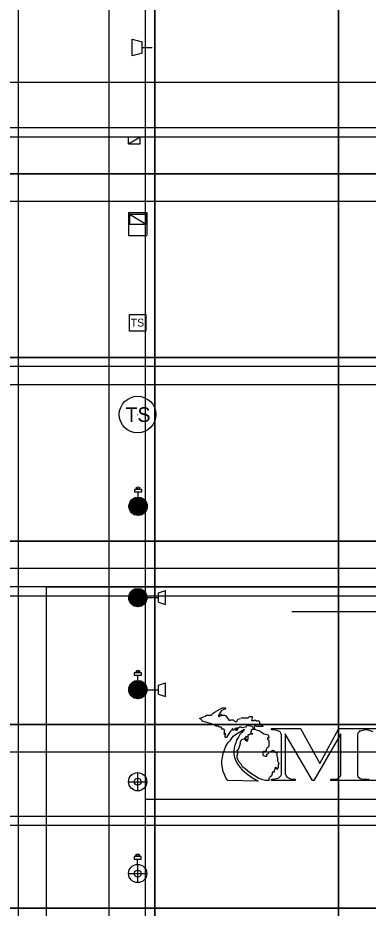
# Model space of a CAD drawing. Extents: x 2146475 to 2147951, y 2147003 to 2148003.
# Drawn here: x 2147543.5 to 2147619.9, y 2147343 to 2147537 of the extents above; entities that cross this region are included whole.
import ezdxf

# ---------------------------------------------------------------- set-up
doc = ezdxf.new("R2010")
doc.units = 0
for name, color, linetype in [('Sheet_Border_Block_LightingInventory', 7, 'Continuous'), ('Sheet_Border_Line_Wt2', 7, 'Continuous'), ('Sheet_Border_Plan_Dual', 7, 'Continuous'), ('Sheet_Border_PlanOverProf1_Grid+Sta+EL_04_040+08_080', 7, 'Continuous'), ('Sheet_Border_PlanOverProf1_Grid+Sta+EL_10_100+20_200', 7, 'Continuous'), ('Sheet_Border_Prof3_Grid+Sta+EL_04_040+08_080', 7, 'Continuous'), ('Sheet_Border_Prof3_Grid+Sta+EL_10_100+20_200', 7, 'Continuous'), ('Sheet_Border_TitleSheet', 7, 'Continuous'), ('Sheet_Border_TitleSheet_ConsultantBlock', 7, 'Continuous'), ('Sheet_Border_XS_Grid', 7, 'Continuous'), ('Signal_Ctrl_TS_Controller_Fdn_Pr_BaseMount_$Ea', 7, 'Continuous'), ('Signal_Ctrl_TS_Controller_Pr_$Ea', 7, 'Continuous'), ('Signal_Mt_All_TS_Ped_Ex_GS', 7, 'Continuous'), ('Signal_Pole_Ped+PushButton_Ex_GS', 7, 'Continuous'), ('Signal_Pole_Ped_Ex_GS', 7, 'Continuous'), ('Signal_Pole_Steel_Ex_GS', 7, 'Continuous'), ('Util_NoID_Ex_Handhole_Round_GS', 7, 'Continuous'), ('Util_NoID_Ex_Handhole_Square_GS', 7, 'Continuous')]:
    doc.layers.add(name, color=color, linetype=linetype)

msp = doc.modelspace()

# ---------------------------------------------------------------- linework, layer by layer
at = {"layer": 'Sheet_Border_Block_LightingInventory'}
for p, q in [((2147549.81, 2147124.95), (2147549.81, 2147412.95)), ((2147549.81, 2147412.95), (2147871.41, 2147412.95))]:
    msp.add_line(p, q, dxfattribs=at)
for points in [[(2147592.2, 2147384.43), (2147593.78, 2147384.43), (2147594.07, 2147384.72), (2147594.64, 2147384.72), (2147594.64, 2147384.43), (2147594.5, 2147383.85), (2147595.08, 2147383.85), (2147595.22, 2147384), (2147595.36, 2147383.85), (2147595.51, 2147383.85), (2147595.51, 2147383.71), (2147595.94, 2147383.85), (2147596.23, 2147383.57), (2147596.23, 2147383.13), (2147596.37, 2147383.13), (2147596.66, 2147382.85), (2147596.66, 2147382.7), (2147596.95, 2147382.7), (2147596.95, 2147382.56), (2147595.65, 2147382.56), (2147595.36, 2147382.7), (2147595.22, 2147382.7), (2147595.08, 2147382.41), (2147595.22, 2147382.27), (2147595.08, 2147382.13), (2147594.93, 2147382.13), (2147594.79, 2147382.41), (2147594.64, 2147382.56), (2147593.92, 2147382.7), (2147593.49, 2147382.85), (2147593.35, 2147382.7), (2147593.2, 2147382.41), (2147592.48, 2147382.27), (2147592.2, 2147382.41), (2147591.91, 2147382.41), (2147591.48, 2147382.13), (2147591.19, 2147381.69), (2147591.04, 2147381.69), (2147591.04, 2147381.84), (2147591.19, 2147381.98), (2147591.33, 2147382.27), (2147591.04, 2147382.13), (2147590.9, 2147382.13), (2147590.76, 2147381.98), (2147590.47, 2147381.69), (2147590.32, 2147382.13), (2147590.18, 2147381.84), (2147589.89, 2147381.55), (2147589.6, 2147381.12), (2147589.03, 2147380.11), (2147588.88, 2147380.11), (2147588.74, 2147380.25), (2147588.74, 2147380.54), (2147588.88, 2147380.97), (2147588.74, 2147380.97), (2147588.6, 2147380.83), (2147588.45, 2147380.97), (2147588.6, 2147381.12), (2147588.6, 2147381.84), (2147588.45, 2147381.98), (2147588.02, 2147381.98), (2147588.02, 2147382.13), (2147587.88, 2147382.27), (2147588.02, 2147382.27), (2147587.88, 2147382.41), (2147587.59, 2147382.41), (2147587.3, 2147382.56), (2147587.01, 2147382.85), (2147586.87, 2147382.56), (2147586.58, 2147382.85), (2147586.44, 2147382.85), (2147586.15, 2147382.99), (2147585.28, 2147383.28), (2147583.7, 2147383.71), (2147583.7, 2147383.85), (2147583.41, 2147384.14), (2147583.41, 2147384.29), (2147583.12, 2147384.29), (2147584.56, 2147384.86), (2147584.56, 2147385.01), (2147585.72, 2147385.01), (2147586.15, 2147385.44), (2147586.58, 2147385.73), (2147587.59, 2147386.3), (2147588.16, 2147386.59), (2147588.74, 2147386.59), (2147588.88, 2147386.45), (2147588.74, 2147386.3), (2147588.6, 2147386.3), (2147588.31, 2147386.16), (2147588.02, 2147386.01), (2147587.88, 2147385.87), (2147587.59, 2147385.44), (2147587.44, 2147385.15), (2147587.3, 2147385.01), (2147587.3, 2147384.72), (2147587.44, 2147384.72), (2147587.59, 2147384.86), (2147587.73, 2147385.15), (2147588.02, 2147385.15), (2147587.73, 2147384.86)], [(2147587.73, 2147384.86), (2147588.16, 2147385.01), (2147588.6, 2147385.01), (2147588.88, 2147384.86), (2147589.17, 2147384.43), (2147589.32, 2147384.29), (2147589.6, 2147383.85), (2147590.04, 2147384), (2147590.47, 2147384), (2147590.76, 2147383.71), (2147591.19, 2147383.57), (2147591.33, 2147383.71), (2147591.33, 2147383.85), (2147591.48, 2147384.14), (2147592.05, 2147384.29)], [(2147621, 2147381.41), (2147619.7, 2147381.84), (2147619.12, 2147381.84), (2147619.12, 2147382.13), (2147627.19, 2147382.13)], [(2147597.96, 2147380.11), (2147597.96, 2147379.82), (2147597.96, 2147379.68), (2147598.24, 2147379.53), (2147598.24, 2147378.24), (2147598.1, 2147377.95), (2147597.96, 2147377.95), (2147597.81, 2147377.81), (2147597.67, 2147377.52), (2147597.67, 2147377.23), (2147597.52, 2147377.09), (2147597.09, 2147377.09), (2147596.95, 2147376.94), (2147596.95, 2147376.37), (2147597.09, 2147376.22), (2147597.52, 2147376.08), (2147597.81, 2147376.08), (2147597.81, 2147376.51), (2147597.96, 2147376.51), (2147598.24, 2147376.8), (2147598.24, 2147376.94), (2147598.1, 2147376.94), (2147598.68, 2147377.09), (2147599.11, 2147377.37), (2147599.4, 2147377.23), (2147599.54, 2147376.94), (2147599.97, 2147376.8), (2147599.97, 2147376.08), (2147600.12, 2147375.79), (2147600.12, 2147375.07), (2147600.4, 2147374.49), (2147600.4, 2147374.35), (2147600.26, 2147374.35), (2147600.26, 2147373.63), (2147599.97, 2147373.2), (2147599.83, 2147373.63), (2147599.68, 2147373.63), (2147599.54, 2147373.49), (2147599.54, 2147373.2), (2147599.4, 2147372.91), (2147599.4, 2147372.62), (2147598.96, 2147372.62), (2147598.96, 2147372.19), (2147598.82, 2147371.76), (2147598.68, 2147371.61), (2147598.53, 2147371.61), (2147598.39, 2147371.33), (2147598.24, 2147371.18), (2147598.24, 2147370.75), (2147597.52, 2147370.75), (2147596.95, 2147370.89), (2147596.08, 2147371.18), (2147594.07, 2147372.48), (2147593.06, 2147373.34), (2147592.48, 2147373.77), (2147592.2, 2147374.35), (2147591.76, 2147374.78), (2147591.48, 2147375.36), (2147591.33, 2147375.79), (2147591.33, 2147376.22), (2147591.48, 2147376.65), (2147591.48, 2147376.94), (2147591.33, 2147377.37), (2147591.62, 2147377.52), (2147591.76, 2147377.95), (2147592.05, 2147378.81), (2147591.91, 2147378.96), (2147592.05, 2147379.1), (2147592.2, 2147379.53), (2147592.34, 2147379.68), (2147592.77, 2147379.82), (2147592.92, 2147379.68), (2147593.06, 2147380.11), (2147593.35, 2147380.4), (2147593.2, 2147379.82), (2147593.2, 2147379.39), (2147593.49, 2147379.68), (2147593.64, 2147379.68), (2147593.35, 2147379.25), (2147593.64, 2147379.53), (2147593.78, 2147379.82), (2147593.78, 2147380.69), (2147593.92, 2147380.83), (2147594.07, 2147380.83), (2147594.21, 2147380.97), (2147594.79, 2147380.97), (2147594.79, 2147380.97), (2147594.5, 2147380.97), (2147594.36, 2147381.26), (2147594.5, 2147381.55), (2147594.5, 2147381.84), (2147594.64, 2147381.98), (2147595.22, 2147381.98), (2147595.51, 2147381.84), (2147595.94, 2147381.69), (2147596.08, 2147381.69), (2147596.37, 2147381.55), (2147596.52, 2147381.41), (2147597.24, 2147380.97), (2147598.1, 2147380.69), (2147598.24, 2147379.97)], [(2147598.24, 2147379.97), (2147598.1, 2147380.11)], [(2147627.62, 2147370.75), (2147619.12, 2147370.75), (2147619.12, 2147371.04), (2147620.13, 2147371.04)]]:
    msp.add_lwpolyline(points, dxfattribs=at)
for points in [[(2147605.16, 2147382.13), (2147609.33, 2147374.49), (2147613.51, 2147382.13), (2147619.7, 2147382.13), (2147619.7, 2147381.84), (2147619.27, 2147381.84), (2147618.12, 2147381.55), (2147617.97, 2147381.55), (2147617.97, 2147381.41), (2147617.68, 2147381.12), (2147617.54, 2147380.83), (2147617.54, 2147371.9), (2147617.68, 2147371.61), (2147618.12, 2147371.18), (2147618.69, 2147371.04), (2147619.7, 2147371.04), (2147619.7, 2147370.75), (2147611.78, 2147370.75), (2147611.78, 2147371.04), (2147612.93, 2147371.04), (2147613.36, 2147371.18), (2147613.51, 2147371.47), (2147613.8, 2147371.61), (2147613.94, 2147371.9), (2147613.94, 2147380.97), (2147608.04, 2147370.75), (2147607.75, 2147370.75), (2147601.84, 2147380.97), (2147601.84, 2147372.33), (2147602.13, 2147371.61), (2147602.56, 2147371.33), (2147603.14, 2147371.04), (2147604, 2147371.04), (2147604, 2147370.75), (2147598.82, 2147370.75), (2147598.82, 2147371.04), (2147598.96, 2147371.04), (2147599.97, 2147371.18), (2147600.4, 2147371.33), (2147600.55, 2147371.47), (2147600.84, 2147371.76), (2147600.98, 2147372.05), (2147600.98, 2147380.83), (2147600.84, 2147381.12), (2147600.69, 2147381.41), (2147600.4, 2147381.55), (2147599.97, 2147381.69), (2147599.25, 2147381.84), (2147598.82, 2147381.84), (2147598.82, 2147382.13)], [(2147589.32, 2147370.75), (2147588.88, 2147371.33), (2147588.6, 2147372.05), (2147588.31, 2147372.77), (2147588.02, 2147374.35), (2147588.02, 2147375.07), (2147588.31, 2147376.65), (2147588.88, 2147378.24), (2147589.32, 2147378.96), (2147589.89, 2147379.53), (2147590.47, 2147380.4), (2147591.19, 2147380.97), (2147592.92, 2147381.98), (2147592.34, 2147381.26), (2147591.91, 2147380.83), (2147591.62, 2147380.25), (2147591.19, 2147379.53), (2147591.04, 2147378.96), (2147590.76, 2147378.24), (2147590.61, 2147377.37), (2147590.61, 2147376.51), (2147590.76, 2147375.79), (2147591.19, 2147374.78), (2147591.62, 2147374.06), (2147592.34, 2147373.2), (2147593.35, 2147372.33), (2147594.5, 2147371.47), (2147595.94, 2147370.61)]]:
    msp.add_lwpolyline(points, close=True, dxfattribs=at)
at = {"layer": 'Sheet_Border_Line_Wt2'}
msp.add_line((2147543.69, 2147124.95), (2147543.69, 2147920.95), dxfattribs=at)
at = {"layer": 'Sheet_Border_Plan_Dual'}
msp.add_line((2146555.41, 2147522.95), (2147871.41, 2147522.95), dxfattribs=at)
at = {"layer": 'Sheet_Border_PlanOverProf1_Grid+Sta+EL_04_040+08_080'}
for p, q in [((2146555.41, 2147522.95), (2147871.41, 2147522.95)), ((2147813.41, 2147512.95), (2146613.41, 2147512.95)), ((2147563.41, 2147512.95), (2147563.41, 2147138.95)), ((2147613.41, 2147512.95), (2147613.41, 2147138.95)), ((2147813.41, 2147462.95), (2146613.41, 2147462.95)), ((2147813.41, 2147412.95), (2146613.41, 2147412.95)), ((2147813.41, 2147362.95), (2146613.41, 2147362.95))]:
    msp.add_line(p, q, dxfattribs=at)
at = {"layer": 'Sheet_Border_PlanOverProf1_Grid+Sta+EL_10_100+20_200'}
for p, q in [((2146555.41, 2147522.95), (2147871.41, 2147522.95)), ((2147813.41, 2147502.95), (2146613.41, 2147502.95)), ((2147573.41, 2147502.95), (2147573.41, 2147158.95)), ((2147613.41, 2147502.95), (2147613.41, 2147158.95)), ((2147813.41, 2147462.95), (2146613.41, 2147462.95)), ((2147813.41, 2147422.95), (2146613.41, 2147422.95)), ((2147813.41, 2147382.95), (2146613.41, 2147382.95)), ((2147813.41, 2147342.95), (2146613.41, 2147342.95))]:
    msp.add_line(p, q, dxfattribs=at)
at = {"layer": 'Sheet_Border_Prof3_Grid+Sta+EL_04_040+08_080'}
for p, q in [((2147563.41, 2147910.95), (2147563.41, 2147136.95)), ((2147613.41, 2147910.95), (2147613.41, 2147136.95)), ((2147813.41, 2147510.95), (2146613.41, 2147510.95)), ((2147813.41, 2147460.95), (2146613.41, 2147460.95)), ((2147813.41, 2147410.95), (2146613.41, 2147410.95)), ((2147813.41, 2147360.95), (2146613.41, 2147360.95))]:
    msp.add_line(p, q, dxfattribs=at)
at = {"layer": 'Sheet_Border_Prof3_Grid+Sta+EL_10_100+20_200'}
for p, q in [((2147573.41, 2147896.95), (2147573.41, 2147152.95)), ((2147613.41, 2147896.95), (2147613.41, 2147152.95)), ((2147813.41, 2147496.95), (2146613.41, 2147496.95)), ((2147813.41, 2147456.95), (2146613.41, 2147456.95)), ((2147813.41, 2147416.95), (2146613.41, 2147416.95)), ((2147813.41, 2147376.95), (2146613.41, 2147376.95))]:
    msp.add_line(p, q, dxfattribs=at)
at = {"layer": 'Sheet_Border_TitleSheet'}
for p, q in [((2147571.41, 2147366.72), (2147871.41, 2147366.72)), ((2147571.41, 2147124.95), (2147571.41, 2147366.72))]:
    msp.add_line(p, q, dxfattribs=at)
at = {"layer": 'Sheet_Border_TitleSheet_ConsultantBlock'}
for p, q in [((2147571.41, 2147366.72), (2147571.41, 2147666.72)), ((2147603.25, 2147407.59), (2147769.16, 2147407.59))]:
    msp.add_line(p, q, dxfattribs=at)
at = {"layer": 'Sheet_Border_XS_Grid'}
for p, q in [((2147573.41, 2147142.95), (2147573.41, 2147902.95)), ((2147613.41, 2147142.95), (2147613.41, 2147902.95)), ((2146573.41, 2147502.95), (2147853.41, 2147502.95)), ((2146573.41, 2147462.95), (2147853.41, 2147462.95)), ((2146573.41, 2147422.95), (2147853.41, 2147422.95)), ((2146573.41, 2147382.95), (2147853.41, 2147382.95)), ((2146573.41, 2147342.95), (2147853.41, 2147342.95))]:
    msp.add_line(p, q, dxfattribs=at)
at = {"layer": 'Signal_Ctrl_TS_Controller_Fdn_Pr_BaseMount_$Ea'}
for p, q in [((2147567.7, 2147494.51), (2147571.7, 2147494.51)), ((2147567.7, 2147494.51), (2147567.7, 2147489.52)), ((2147567.87, 2147494.18), (2147567.87, 2147492.01)), ((2147567.87, 2147494.18), (2147571.53, 2147494.18)), ((2147567.87, 2147494.18), (2147571.53, 2147492.01)), ((2147571.53, 2147494.18), (2147571.53, 2147492.01)), ((2147571.7, 2147494.51), (2147571.7, 2147489.52)), ((2147567.7, 2147492.01), (2147571.7, 2147492.01)), ((2147567.7, 2147489.52), (2147571.7, 2147489.52))]:
    msp.add_line(p, q, dxfattribs=at)
at = {"layer": 'Signal_Ctrl_TS_Controller_Pr_$Ea'}
for p, q in [((2147567.7, 2147511.05), (2147570.19, 2147511.05)), ((2147567.7, 2147509.52), (2147567.7, 2147511.05)), ((2147567.7, 2147509.52), (2147570.19, 2147511.05)), ((2147570.19, 2147509.52), (2147570.19, 2147511.05)), ((2147567.7, 2147509.52), (2147570.19, 2147509.52))]:
    msp.add_line(p, q, dxfattribs=at)
at = {"layer": 'Signal_Mt_All_TS_Ped_Ex_GS'}
for p, q in [((2147568.46, 2147528.7), (2147568.46, 2147532.3)), ((2147568.46, 2147532.3), (2147570.66, 2147531.75)), ((2147570.66, 2147529.25), (2147570.66, 2147531.75)), ((2147570.66, 2147530.5), (2147572.85, 2147530.5)), ((2147570.66, 2147529.25), (2147568.46, 2147528.7)), ((2147574.19, 2147411.63), (2147575.71, 2147412.14)), ((2147574.19, 2147409.63), (2147574.19, 2147411.63)), ((2147575.71, 2147409.14), (2147575.71, 2147412.14)), ((2147571.69, 2147410.62), (2147574.19, 2147410.62)), ((2147574.19, 2147409.63), (2147575.71, 2147409.14)), ((2147574.2, 2147391.56), (2147575.71, 2147392.07)), ((2147575.71, 2147389.08), (2147575.71, 2147392.07)), ((2147571.7, 2147390.56), (2147574.2, 2147390.56)), ((2147574.2, 2147389.56), (2147574.2, 2147391.56)), ((2147574.2, 2147389.56), (2147575.71, 2147389.08))]:
    msp.add_line(p, q, dxfattribs=at)
at = {"layer": 'Signal_Pole_Ped+PushButton_Ex_GS'}
for p, q in [((2147569.29, 2147434.45), (2147569.58, 2147434.45)), ((2147569.58, 2147434.45), (2147569.58, 2147434.2)), ((2147569.75, 2147432.49), (2147569.75, 2147433.66)), ((2147569.93, 2147434.45), (2147570.22, 2147434.45)), ((2147569.93, 2147434.45), (2147569.93, 2147434.2)), ((2147569.75, 2147432.49), (2147569.75, 2147432.49)), ((2147569.24, 2147394.51), (2147569.53, 2147394.51)), ((2147569.53, 2147394.51), (2147569.53, 2147394.26)), ((2147569.88, 2147394.51), (2147570.17, 2147394.51)), ((2147569.88, 2147394.51), (2147569.88, 2147394.26)), ((2147569.71, 2147392.55), (2147569.71, 2147393.72)), ((2147569.71, 2147392.55), (2147569.71, 2147392.55)), ((2147569.19, 2147354.45), (2147569.48, 2147354.45)), ((2147569.48, 2147354.45), (2147569.48, 2147354.2)), ((2147569.66, 2147352.49), (2147569.66, 2147353.66)), ((2147569.83, 2147354.45), (2147570.13, 2147354.45)), ((2147569.83, 2147354.45), (2147569.83, 2147354.2)), ((2147569.66, 2147352.49), (2147569.66, 2147352.49))]:
    msp.add_line(p, q, dxfattribs=at)
for points in [[(2147568.97, 2147433.66), (2147570.54, 2147433.66), (2147570.54, 2147434.2), (2147568.97, 2147434.2)], [(2147568.92, 2147393.72), (2147570.49, 2147393.72), (2147570.49, 2147394.26), (2147568.92, 2147394.26)], [(2147568.88, 2147353.66), (2147570.44, 2147353.66), (2147570.44, 2147354.2), (2147568.88, 2147354.2)]]:
    msp.add_lwpolyline(points, close=True, dxfattribs=at)
for centre in [(2147569.75, 2147434.45), (2147569.71, 2147394.51), (2147569.66, 2147354.45)]:
    msp.add_ellipse(centre, major_axis=(0.467, 0), ratio=0.42688, start_param=0, end_param=3.141593, dxfattribs=at)
at = {"layer": 'Signal_Pole_Ped_Ex_GS'}
for p, q in [((2147567.77, 2147430.62), (2147571.74, 2147430.62)), ((2147571.73, 2147430.75), (2147567.78, 2147430.75)), ((2147571.71, 2147430.87), (2147567.8, 2147430.87)), ((2147571.68, 2147431), (2147567.83, 2147431)), ((2147571.65, 2147431.12), (2147567.86, 2147431.12)), ((2147571.6, 2147431.25), (2147567.91, 2147431.25)), ((2147571.55, 2147431.37), (2147567.96, 2147431.37)), ((2147571.48, 2147431.49), (2147568.03, 2147431.49)), ((2147568.11, 2147431.62), (2147571.4, 2147431.62)), ((2147571.31, 2147431.74), (2147568.2, 2147431.74)), ((2147571.2, 2147431.87), (2147568.31, 2147431.87)), ((2147571.08, 2147431.99), (2147568.44, 2147431.99)), ((2147570.92, 2147432.12), (2147568.59, 2147432.12)), ((2147570.72, 2147432.24), (2147568.79, 2147432.24)), ((2147570.45, 2147432.37), (2147569.06, 2147432.37)), ((2147571.75, 2147430.5), (2147567.76, 2147430.5)), ((2147571.74, 2147430.38), (2147567.77, 2147430.38)), ((2147571.73, 2147430.25), (2147567.78, 2147430.25)), ((2147571.71, 2147430.13), (2147567.8, 2147430.13)), ((2147571.68, 2147430), (2147567.83, 2147430)), ((2147571.65, 2147429.88), (2147567.86, 2147429.88)), ((2147567.91, 2147429.75), (2147571.6, 2147429.75)), ((2147571.55, 2147429.63), (2147567.96, 2147429.63)), ((2147571.48, 2147429.5), (2147568.03, 2147429.5)), ((2147571.4, 2147429.38), (2147568.11, 2147429.38)), ((2147571.31, 2147429.26), (2147568.2, 2147429.26)), ((2147571.2, 2147429.13), (2147568.31, 2147429.13)), ((2147571.07, 2147429.01), (2147568.44, 2147429.01)), ((2147570.92, 2147428.88), (2147568.59, 2147428.88)), ((2147568.79, 2147428.76), (2147570.72, 2147428.76)), ((2147570.45, 2147428.63), (2147569.06, 2147428.63)), ((2147569.84, 2147428.51), (2147569.67, 2147428.51)), ((2147571.59, 2147411.25), (2147567.81, 2147411.25)), ((2147571.55, 2147411.37), (2147567.85, 2147411.37)), ((2147571.49, 2147411.49), (2147567.91, 2147411.49)), ((2147571.43, 2147411.62), (2147567.97, 2147411.62)), ((2147568.05, 2147411.74), (2147571.35, 2147411.74)), ((2147571.26, 2147411.87), (2147568.14, 2147411.87)), ((2147571.15, 2147411.99), (2147568.25, 2147411.99)), ((2147571.02, 2147412.12), (2147568.38, 2147412.12)), ((2147570.86, 2147412.24), (2147568.54, 2147412.24)), ((2147570.67, 2147412.37), (2147568.73, 2147412.37)), ((2147570.4, 2147412.49), (2147569, 2147412.49)), ((2147567.71, 2147410.75), (2147571.69, 2147410.75)), ((2147571.69, 2147410.62), (2147567.71, 2147410.62)), ((2147571.69, 2147410.5), (2147567.71, 2147410.5)), ((2147571.68, 2147410.87), (2147567.72, 2147410.87)), ((2147571.68, 2147410.38), (2147567.72, 2147410.38)), ((2147571.66, 2147411), (2147567.74, 2147411)), ((2147571.66, 2147410.25), (2147567.74, 2147410.25)), ((2147571.63, 2147411.12), (2147567.77, 2147411.12)), ((2147571.63, 2147410.13), (2147567.77, 2147410.13)), ((2147571.59, 2147410), (2147567.81, 2147410)), ((2147567.85, 2147409.88), (2147571.55, 2147409.88)), ((2147571.49, 2147409.75), (2147567.91, 2147409.75)), ((2147571.43, 2147409.63), (2147567.97, 2147409.63)), ((2147571.35, 2147409.5), (2147568.05, 2147409.5)), ((2147571.26, 2147409.38), (2147568.14, 2147409.38)), ((2147571.15, 2147409.26), (2147568.25, 2147409.26)), ((2147571.02, 2147409.13), (2147568.38, 2147409.13)), ((2147570.86, 2147409.01), (2147568.54, 2147409.01)), ((2147568.73, 2147408.88), (2147570.67, 2147408.88)), ((2147570.4, 2147408.76), (2147569, 2147408.76)), ((2147569.79, 2147408.63), (2147569.61, 2147408.63)), ((2147571.15, 2147391.93), (2147568.26, 2147391.93)), ((2147571.03, 2147392.05), (2147568.39, 2147392.05)), ((2147570.87, 2147392.18), (2147568.54, 2147392.18)), ((2147570.67, 2147392.3), (2147568.74, 2147392.3)), ((2147570.4, 2147392.42), (2147569.01, 2147392.42)), ((2147571.7, 2147390.56), (2147567.71, 2147390.56)), ((2147567.72, 2147390.68), (2147571.69, 2147390.68)), ((2147571.69, 2147390.43), (2147567.72, 2147390.43)), ((2147571.68, 2147390.81), (2147567.73, 2147390.81)), ((2147571.68, 2147390.31), (2147567.73, 2147390.31)), ((2147571.66, 2147390.93), (2147567.75, 2147390.93)), ((2147571.66, 2147390.19), (2147567.75, 2147390.19)), ((2147571.64, 2147391.06), (2147567.78, 2147391.06)), ((2147571.64, 2147390.06), (2147567.78, 2147390.06)), ((2147571.6, 2147391.18), (2147567.81, 2147391.18)), ((2147571.6, 2147389.94), (2147567.81, 2147389.94)), ((2147571.55, 2147391.31), (2147567.86, 2147391.31)), ((2147571.5, 2147391.43), (2147567.92, 2147391.43)), ((2147571.43, 2147391.55), (2147567.98, 2147391.55)), ((2147568.06, 2147391.68), (2147571.35, 2147391.68)), ((2147571.26, 2147391.8), (2147568.15, 2147391.8)), ((2147567.86, 2147389.81), (2147571.55, 2147389.81)), ((2147571.5, 2147389.69), (2147567.92, 2147389.69)), ((2147571.43, 2147389.56), (2147567.98, 2147389.56)), ((2147571.35, 2147389.44), (2147568.06, 2147389.44)), ((2147571.26, 2147389.32), (2147568.15, 2147389.32)), ((2147571.15, 2147389.19), (2147568.26, 2147389.19)), ((2147571.03, 2147389.07), (2147568.39, 2147389.07)), ((2147570.87, 2147388.94), (2147568.54, 2147388.94)), ((2147568.74, 2147388.82), (2147570.67, 2147388.82)), ((2147570.4, 2147388.69), (2147569.01, 2147388.69)), ((2147569.8, 2147388.57), (2147569.62, 2147388.57))]:
    msp.add_line(p, q, dxfattribs=at)
for centre in [(2147569.76, 2147430.5), (2147569.7, 2147410.62), (2147569.71, 2147390.56)]:
    msp.add_circle(centre, 1.99, dxfattribs=at)
at = {"layer": 'Signal_Pole_Steel_Ex_GS'}
for p, q in [((2147569.66, 2147372.49), (2147569.66, 2147368.51)), ((2147567.67, 2147370.5), (2147571.64, 2147370.5)), ((2147569.66, 2147352.49), (2147569.66, 2147348.51)), ((2147567.67, 2147350.5), (2147571.65, 2147350.5))]:
    msp.add_line(p, q, dxfattribs=at)
for centre, radius in [((2147569.66, 2147370.5), 1.99), ((2147569.66, 2147370.5), 0.757), ((2147569.66, 2147350.51), 1.99), ((2147569.66, 2147350.5), 0.757)]:
    msp.add_circle(centre, radius, dxfattribs=at)
at = {"layer": 'Util_NoID_Ex_Handhole_Round_GS'}
for radius in [4, 0.0104]:
    msp.add_circle((2147569.66, 2147450.5), radius, dxfattribs=at)
at = {"layer": 'Util_NoID_Ex_Handhole_Square_GS'}
msp.add_lwpolyline([(2147567.86, 2147472.3), (2147571.46, 2147472.3), (2147571.46, 2147468.7), (2147567.86, 2147468.7)], close=True, dxfattribs=at)

# ---------------------------------------------------------------- texts
at = {"layer": 'Util_NoID_Ex_Handhole_Round_GS'}
msp.add_text('TS', height=3.203, dxfattribs=at).set_placement((2147567, 2147448.9))
at = {"layer": 'Util_NoID_Ex_Handhole_Square_GS'}
msp.add_text('TS', height=1.728, dxfattribs=at).set_placement((2147568.13, 2147469.67))

doc.saveas('drawing.dxf')
